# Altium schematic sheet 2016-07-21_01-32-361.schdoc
size 331 x 190 mm; SheetNumber: 1; SheetTotal: 1
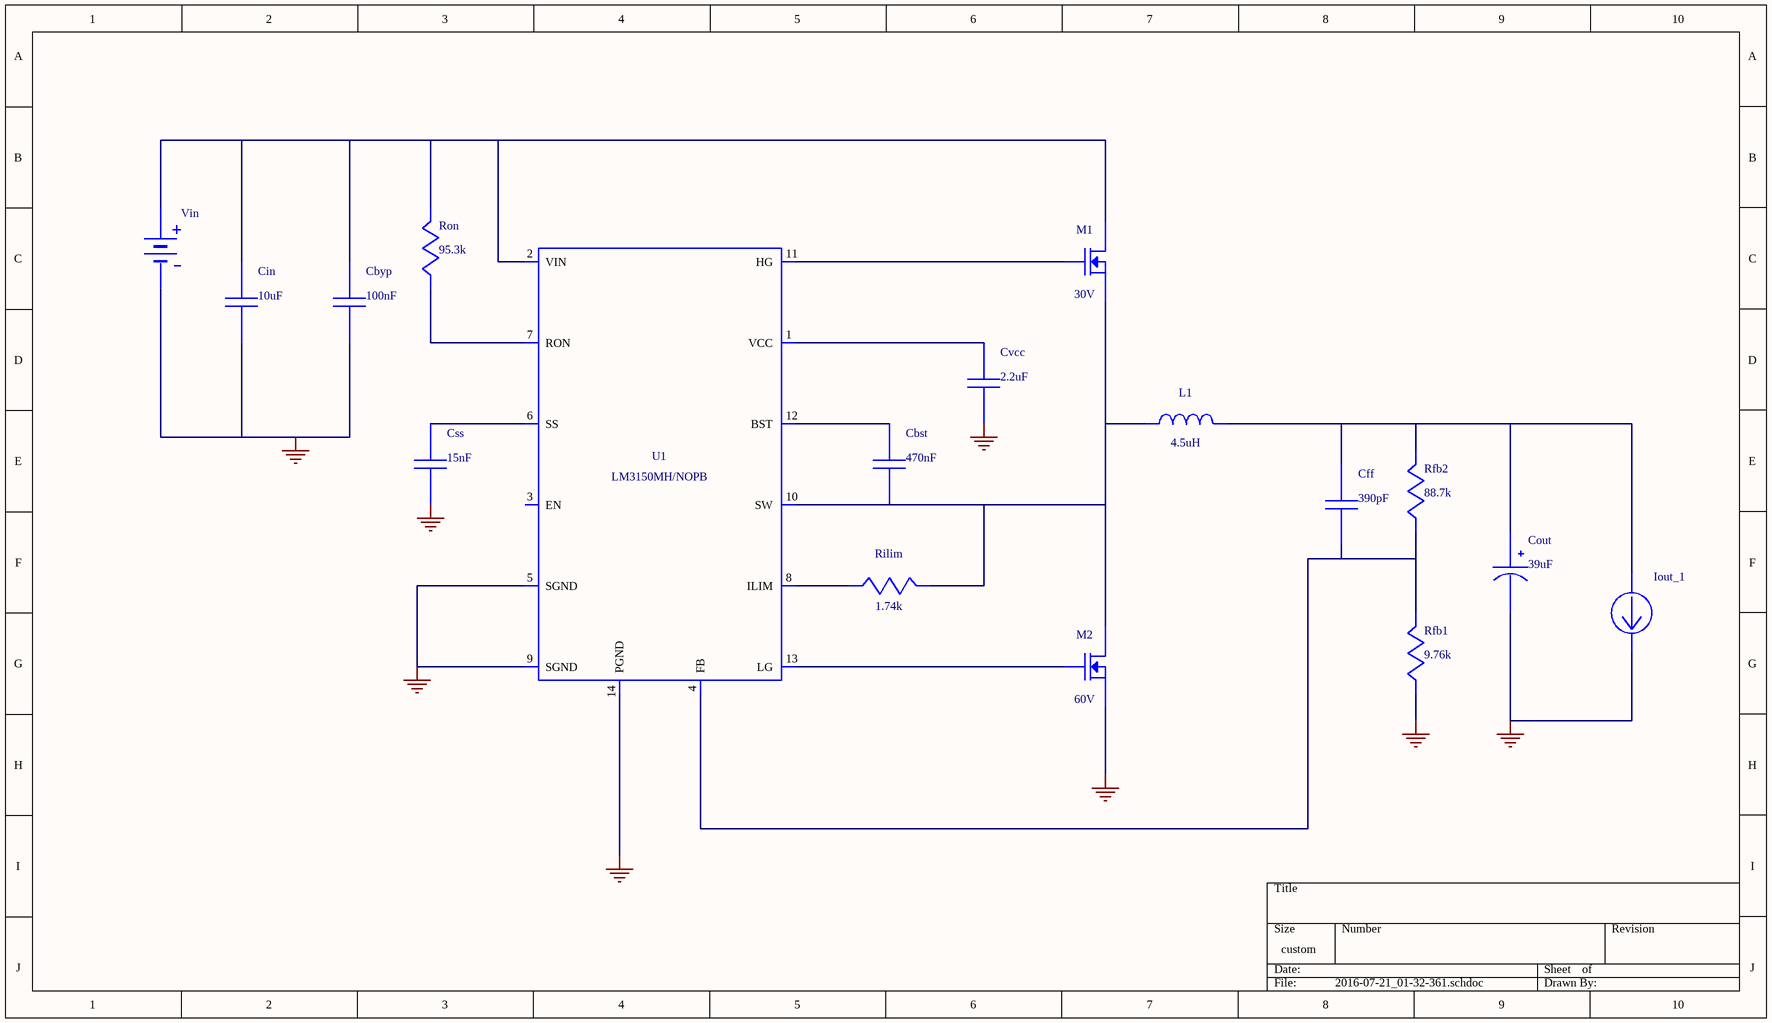
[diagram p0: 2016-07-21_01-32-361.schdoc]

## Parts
Cbst  value 470nF  (hidden comment: EMK212B7474KD-T)
Cbyp  value 100nF  (hidden comment: C0805C104K5RACTU)
Cff  value 390pF  (hidden comment: CC0805KRX7R9BB391)
Cin  value 10uF  (hidden comment: GRM32ER7YA106KA12L)
Cout  value 39uF  (hidden comment: GENERIC_CAP_POLARIZED)
Css  value 15nF  (hidden comment: CC0805KRX7R9BB153)
Cvcc  value 2.2uF  (hidden comment: EMK212B7225KG-T)
Iout_1  WB_CURRENT_LOAD  (value not drawn)
L1  value 4.5uH  (hidden comment: SRR1208-4R5ML)
M1  value 30V  (hidden comment: CSD17507Q5A)
M2  value 60V  (hidden comment: CSD18537NQ5A)
Rfb1  value 9.76k  (hidden comment: ERJ-6ENF9761V)
Rfb2  value 88.7k  (hidden comment: ERJ-6ENF8872V)
Rilim  value 1.74k  (hidden comment: ERJ-6ENF1741V)
Ron  value 95.3k  (hidden comment: ERJ-6ENF9532V)
U1  LM3150MH/NOPB
Vin  WB_BATTERY  (value not drawn)

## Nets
0: Cbyp.2 Cin.2 Cout.2(-) Css.2 Cvcc.2 Iout_1.2(-) M2.1(Source) M2.2(Source) M2.3(Source) Rfb1.2 U1.5(SGND) U1.9(SGND) U1.14(PGND) U1.15(DAP) Vin.2(-)
NetCbst_1: Cbst.1 U1.12(BST)
NetCbst_2: Cbst.2 L1.1 M1.1(Source) M1.2(Source) M1.3(Source) M2.5(Drain) M2.6(Drain) M2.7(Drain) M2.8(Drain) M2.9(Drain) Rilim.1 U1.10(SW)
NetCbyp_1: Cbyp.1 Cin.1 M1.5(Drain) M1.6(Drain) M1.7(Drain) M1.8(Drain) M1.9(Drain) Ron.1 U1.2(VIN) Vin.1(+)
NetCff_1: Cff.1 Cout.1(+) Iout_1.1(+) L1.2 Rfb2.1
NetCff_2: Cff.2 Rfb1.1 Rfb2.2 U1.4(FB)
NetCss_1: Css.1 U1.6(SS)
NetCvcc_1: Cvcc.1 U1.1(VCC)
NetM1_4: M1.4(Gate) U1.11(HG)
NetM2_4: M2.4(Gate) U1.13(LG)
NetRilim_2: Rilim.2 U1.8(ILIM)
NetRon_2: Ron.2 U1.7(RON)

Not connected (* = marked no-connect by the designer): U1 3(EN)

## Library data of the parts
Cbst = EMK212B7474KD-T: Manufacturer Name: Taiyo Yuden
Cbyp = C0805C104K5RACTU: Manufacturer Name: Kemet
Cff = CC0805KRX7R9BB391: CC0805KRX7R9BB39; Manufacturer Name: Yageo America
Cin = GRM32ER7YA106KA12L: GRM32ER7YA106KA1; Manufacturer Name: MuRata
Cout = GENERIC_CAP_POLARIZED: 16SVPC39MV; Manufacturer Name: Panasonic
Css = CC0805KRX7R9BB153: CC0805KRX7R9BB15; Manufacturer Name: Yageo America
Cvcc = EMK212B7225KG-T: Manufacturer Name: Taiyo Yuden
L1 = SRR1208-4R5ML: Manufacturer Name: Bourns
M1 = CSD17507Q5A: Manufacturer Name: Texas Instruments
M2 = CSD18537NQ5A: Manufacturer Name: Texas Instruments
Rfb1 = ERJ-6ENF9761V: Manufacturer Name: Panasonic
Rfb2 = ERJ-6ENF8872V: Manufacturer Name: Panasonic
Rilim = ERJ-6ENF1741V: Manufacturer Name: Panasonic
Ron = ERJ-6ENF9532V: Manufacturer Name: Panasonic
U1 = LM3150MH/NOPB: Manufacturer Name: Texas Instruments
